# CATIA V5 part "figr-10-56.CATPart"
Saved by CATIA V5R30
Part number: Part1
Bounding box of the stored display mesh (mm): x -101.896 to 127.212, y -67.72 to 67.298, z 0 to 0
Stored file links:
  D:\PROJECTS\CATIA V56R 2020\Resources\Parts File\c10_catia_v5_6r2020_prt\figr-10-56.CATPart
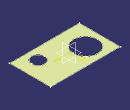
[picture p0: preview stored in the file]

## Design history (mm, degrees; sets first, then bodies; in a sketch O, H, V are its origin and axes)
Body1 (main body)
  Sketch1 on xy-plane, origin (0, 0, 0), H (1, 0, 0), V (0, 1, 0)
    line L1 (-101.8963, 67.298) -> (127.2122, 67.298)
    line L2 (127.2122, 67.298) -> (127.2122, -67.7199)
    line L3 (127.2122, -67.7199) -> (-101.8963, -67.7199)
    line L4 (-101.8963, -67.7199) -> (-101.8963, 67.298)
    horizontal: L1 H, L3 H
    vertical: L2 V, L4 V
  Sketch2 on xy-plane, origin (0, 0, 0), H (1, 0, 0), V (0, 1, 0)
    circle A1 centre (-45.2964, 9.2296) radius 39.3004
    circle A2 centre (71.0804, -29.9585) radius 20.9926
  Fill1: Boundary Sketch1, InnerBoundaries {fillinnerboundary Boundaries Sketch2}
